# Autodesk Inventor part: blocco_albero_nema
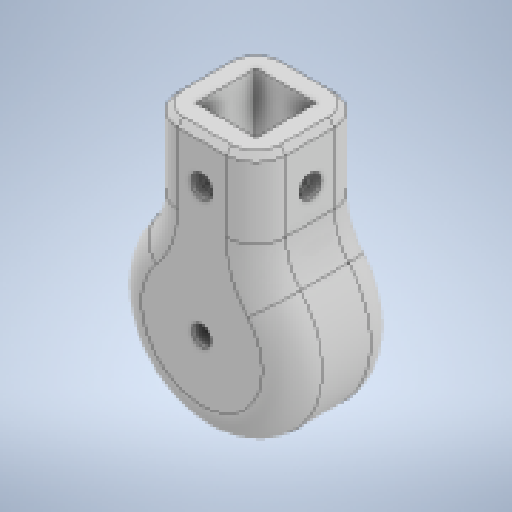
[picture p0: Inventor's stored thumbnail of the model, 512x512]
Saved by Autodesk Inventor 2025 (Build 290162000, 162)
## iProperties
Created: 2026-03
Part Number: blocco_albero_nema
Material: Generico
Document SubType Name: Modeling
Designer: R5800u
Density: 1 g/cm^3
Appearance: Default
Author: R5800u
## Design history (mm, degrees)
sketch "Schizzo1"
  geometry: L1 (-2.646, 3)-(2.646, 3); L2 (0, 0)-(0, 30); L3 (-18, 24)-(18, 24); L4 (18, 24)-(18, 58); L5 (18, 58)-(-18, 58); L6 (-18, 58)-(-18, 24); A1 r 30 centre (0, 0) between (0, 30) and (-18, 24); A2 r 4 centre (0, 0) between (-2.646, 3) and (2.646, 3); 2 further points
  constraints: 12 end point, 4 point on circle, 2 centre point, 2 coincident, 2 horizontal, 2 parallel, 1 perpendicular, 1 vertical, 1 other
  dimensions: "d0" = 60 diameter of A1; "d1" = 8 diameter of A2; "d2" = 3 distance from line of point (0, 0) L1; "d5" = 36 distance of L4.end L5.end; "d6" = 34 distance of L3.end L4.end
extrude "Estrusione1" new body sketch "Schizzo1" stored distance "d3" = 36; taper "d4" = 0 deg
sketch "Schizzo2"
  geometry: L1 (8, -28)-(28, -28); L2 (28, -28)-(28, -8); L3 (28, -8)-(8, -8); L4 (8, -8)-(8, -28); L5 (8, -28)-(28, -8); L6 (28, -28)-(8, -8); 2 further points
  constraints: 12 end point, 2 midpoint, 2 parallel, 1 horizontal, 1 perpendicular
  dimensions: "d7" = 20 distance of L3.end L2.end; "d8" = 20 distance of L2.end L1.end
extrude "Estrusione2" cut sketch "Schizzo2" distance "d9" = 30; taper "d10" = 0 deg
fillet "Raccordo1" dims "d11" = 20
fillet "Raccordo2" dims "d12" = 10
fillet "Raccordo3" dims "d13" = 4
sketch "Schizzo3"
  geometry: C1 r 4 at (0, 0); A1 r 4 centre (0, 0) between (-2.646, 3) and (2.646, 3) reference; 3 further points
  constraints: 1 centre point, 1 coincident
node "Piano di lavoro1"
extrude "Estrusione3" join sketch "Schizzo3" stored distance "d14" = 10; taper "d15" = 0 deg
sketch "Schizzo4"
  geometry: L1 (-8, 32.496)-(-8, 58) reference; L2 (8, 58)-(8, 32.496) reference; L3 (8, 58)-(-8, 58) reference; A1 r 30 centre (-38, 32.496) between (-15.2, 12.998) and (-8, 32.496) reference; A2 r 20 centre (0, 0) between (-15.2, 12.998) and (15.2, 12.998) reference; A3 r 30 centre (38, 32.496) between (8, 32.496) and (15.2, 12.998) reference; 1 further point
hole "Foro1" sketch "Schizzo4" at (0, 0) diameter "d16" = 3.2; stored, may be unused: countersink angle "d20" = 90 deg, drill point angle "d22" = 118 deg; dims "d17" = 6, "d18" = 6.5, "d19" = 10, "d21" = 8
sketch "Schizzo5"
  geometry: L1 (0, 25.504)-(16, 25.504) reference; L2 (8, 25.504)-(8, 10.504); 1 further point
  constraints: 2 end point, 1 midpoint, 1 vertical
  dimensions: "d23" = 15 distance of L2.start L2.end
hole "Foro2" sketch "Schizzo5" at (8, 10.504) diameter "d24" = 4.3; stored, may be unused: countersink angle "d28" = 90 deg, drill point angle "d30" = 118 deg; dims "d25" = 6, "d26" = 7.5, "d27" = 3, "d29" = 8
pattern_circular "Serie circolare1" dims angle "d39" = 360 deg
chamfer "Smusso1" distance "d41" = 2; stored, may be unused: second distance "d42" = 2, angle "d43" = 45 deg
node "Solido1"
node "Linea chiusa proiettata1"
